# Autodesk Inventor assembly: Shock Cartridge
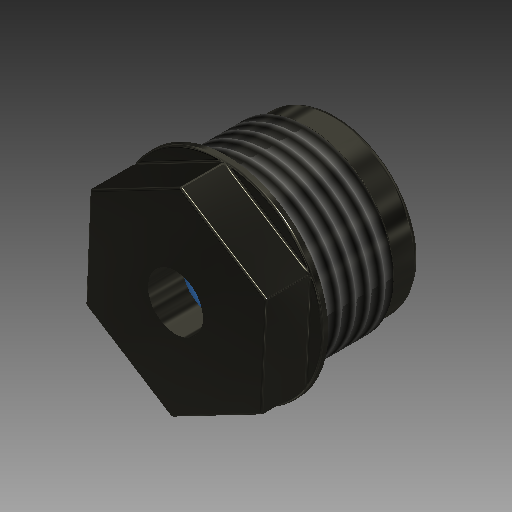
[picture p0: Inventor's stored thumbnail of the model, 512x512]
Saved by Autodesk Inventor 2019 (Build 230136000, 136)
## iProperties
Shininess: 50.0
Compacted: True
Length Units: 11272
Angle Units: 11279
Time Units: 11290
Mass Units: 11286
Length Display Precision: 4
Angle Display Precision: 2
Company: Autodesk
Manager: Lebovitz
Created: 2000-03
Part Number: Shock Cartridge
Project: Inventor Samples
User Status: IN PROGRESS
Document SubType Name: Assembly
Designer: The PD Team
Mass: 0.954454 g
Surface Area: 13.3809 cm^2
Volume: 0.855132 cm^3
Density: 1.11615 g/cm^3
Density: 0.0
Volumn: 0.0
Area: 0.0
PropertySet Name: Model Information
Control State: 0
Master: False
Checked Out: False
Checked Out Date: 2018-05-30
Last Check In Date: 2018-05-30
Author: The PD Team
Revision Number: A
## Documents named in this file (5)
- C:\Users\itools\Desktop\autodesk_inventor_2018_samples\Models\Assemblies\Suspension\Components\Shock Cartridge.iam
- C:\Users\itools\Desktop\autodesk_inventor_2018_samples\Models\Assemblies\Suspension\Components\O-Ring.ipt
- C:\Users\itools\Desktop\autodesk_inventor_2018_samples\Models\Assemblies\Suspension\Components\Shock Cartridge.ipt
- C:\Users\itools\Desktop\autodesk_inventor_2018_samples\Models\Assemblies\Suspension\Components\Shock Cartridge Spacer.ipt
- C:\Users\itools\Desktop\autodesk_inventor_2018_samples\Models\Assemblies\Suspension\Components\Shock Cartridge Cover.ipt
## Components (5 placed, 4 different names)
1. Shock Cartridge:1 — Mate:1, Mate:2, Flush:1, Mate:3, Mate:4, Mate:5, Mate:6
2. O-Ring:1 — Mate:1, Mate:2
3. O-Ring:2 — Flush:1, Mate:3, Mate:7
4. Shock Cartridge Spacer:1 — Mate:4, Mate:7
5. Shock Cartridge Cover:1 — Mate:5, Mate:6
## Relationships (8: Mate 7, Flush 1)
- Mate:1: Shock Cartridge:1 ↔ O-Ring:1
- Mate:2: Shock Cartridge:1 ↔ O-Ring:1
- Flush:1: Shock Cartridge:1 ↔ O-Ring:2
- Mate:3: Shock Cartridge:1 ↔ O-Ring:2
- Mate:4: Shock Cartridge:1 ↔ Shock Cartridge Spacer:1
- Mate:5: Shock Cartridge:1 ↔ Shock Cartridge Cover:1
- Mate:6: Shock Cartridge:1 ↔ Shock Cartridge Cover:1
- Mate:7: O-Ring:2 ↔ Shock Cartridge Spacer:1
